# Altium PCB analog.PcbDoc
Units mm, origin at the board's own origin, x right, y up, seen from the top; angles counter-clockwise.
Board outline 152.4 x 101.6 mm, 2 copper layers (Top Layer, Bottom Layer); 110 components, 92 nets, 331 pads, 16 vias.
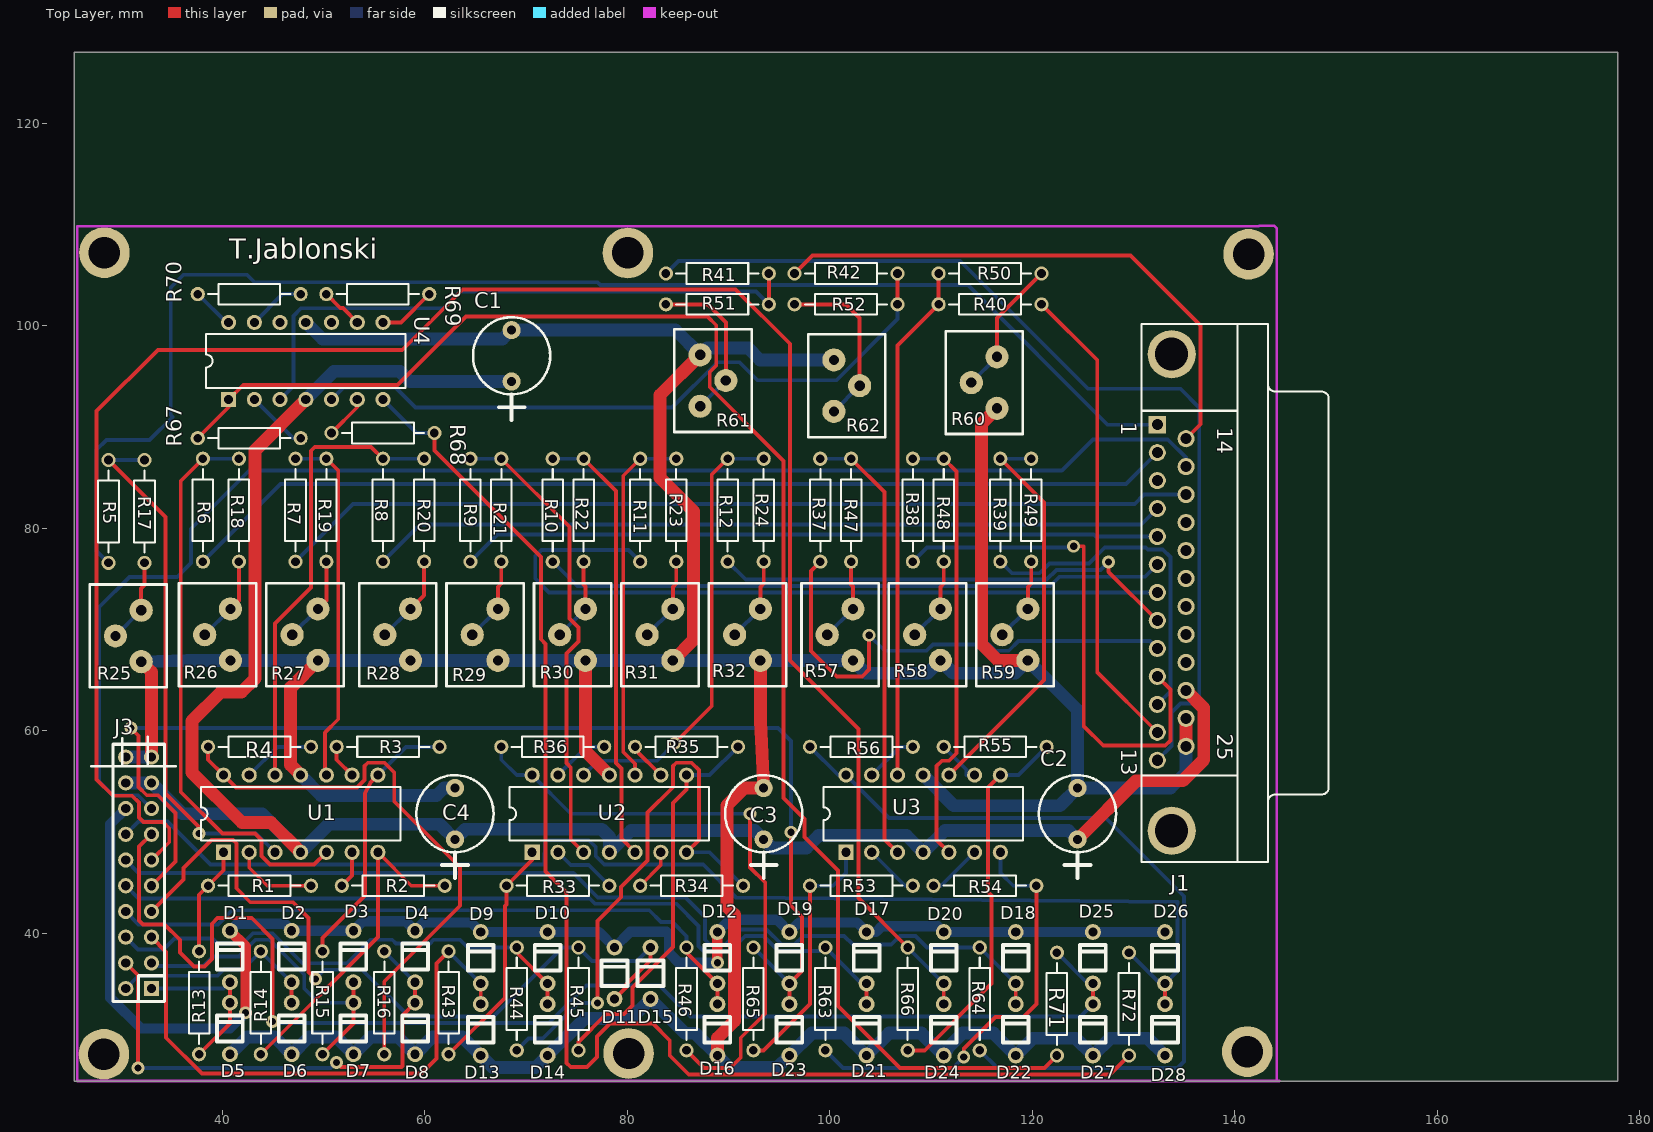
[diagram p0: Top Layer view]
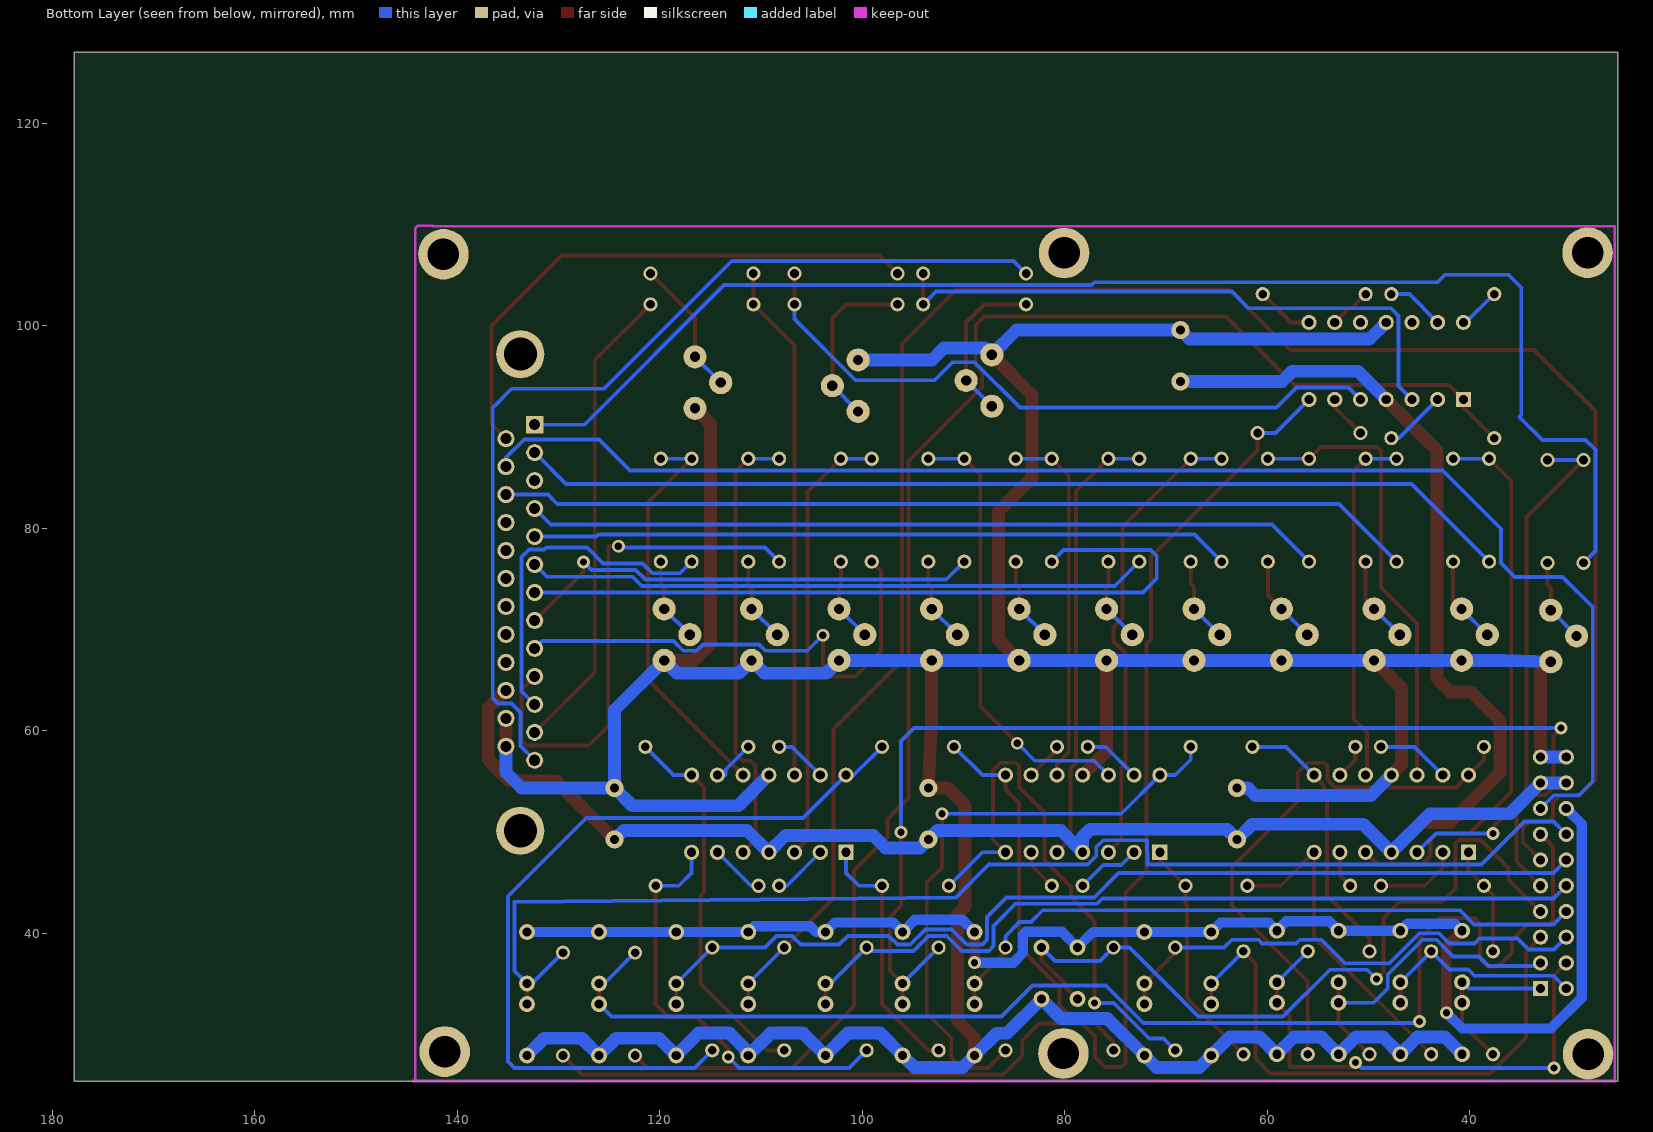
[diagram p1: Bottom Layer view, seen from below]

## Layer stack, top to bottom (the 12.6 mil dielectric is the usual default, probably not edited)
Top Layer: signal copper 0.0356
Dielectric: dielectric 0.32, FR-4, Dk 4.8
Bottom Layer: signal copper 0.0356

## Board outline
25.4,25.4 177.8,25.4 177.8,127 25.4,127

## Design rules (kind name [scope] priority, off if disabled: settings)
Clearance [All] p1: gap=0.254
PolygonConnect [All] p1: connectstyle=Relief reliefconductorwidth=0.254 reliefentries=4 polygonreliefangle="90 Angle"
RoutingVias [All] p1: holewidth=0.711 width=1.27 viastyle="Through Hole" minholewidth=0.711 minwidth=1.27 maxholewidth=0.711 maxwidth=1.27
SilkscreenOverComponentPads [All] p1: minsilkscreentomaskgap=0.254
SolderMaskExpansion [All] p1: expansion=0.102
Width +5V [InNet('+5V')] p1: maxlimit=1.27 minlimit=1.27 preferedwidth=1.27
Width GND [InNet('GND')] p2: maxlimit=1.27 minlimit=1.27 preferedwidth=1.27
Width +3,3V [InNet('+3,3V')] p3: maxlimit=1.016 minlimit=1.016 preferedwidth=1.016
Width all [All] p4: maxlimit=0.381 minlimit=0.381 preferedwidth=0.381
27 further rules are at their usual default settings.

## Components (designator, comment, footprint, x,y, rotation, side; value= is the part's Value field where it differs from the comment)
C1 "100u" RB.2/.3 68.58,94.488 r90 top
C2 "100u" RB.2/.3 124.46,49.276 r90 top
C3 "100u" RB.2/.3 93.472,49.276 r90 top
C4 "100u" RB.2/.3 62.992,49.276 r90 top
D1 "DIODE" DIODE0.2 40.767,35.179 r90 top
D2 "DIODE" DIODE0.2 46.863,35.179 r90 top
D3 "DIODE" DIODE0.2 52.959,35.179 r90 top
D4 "DIODE" DIODE0.2 59.055,35.179 r90 top
D5 "DIODE" DIODE0.2 40.767,28.067 r90 top
D6 "DIODE" DIODE0.2 46.863,28.067 r90 top
D7 "DIODE" DIODE0.2 52.959,28.067 r90 top
D8 "DIODE" DIODE0.2 59.055,28.067 r90 top
D9 "DIODE" DIODE0.2 65.532,35.052 r90 top
D10 "DIODE" DIODE0.2 72.136,35.052 r90 top
D11 "DIODE" DIODE0.2 78.74,33.528 r90 top
D12 "DIODE" DIODE0.2 88.9,35.052 r90 top
D13 "DIODE" DIODE0.2 65.532,27.94 r90 top
D14 "DIODE" DIODE0.2 72.136,27.94 r90 top
D15 "DIODE" DIODE0.2 82.296,33.528 r90 top
D16 "DIODE" DIODE0.2 88.9,27.94 r90 top
D17 "DIODE" DIODE0.2 103.632,35.052 r90 top
D18 "DIODE" DIODE0.2 118.364,35.052 r90 top
D19 "DIODE" DIODE0.2 96.012,35.052 r90 top
D20 "DIODE" DIODE0.2 111.252,35.052 r90 top
D21 "DIODE" DIODE0.2 103.632,27.94 r90 top
D22 "DIODE" DIODE0.2 118.364,27.94 r90 top
D23 "DIODE" DIODE0.2 96.012,27.94 r90 top
D24 "DIODE" DIODE0.2 111.252,27.94 r90 top
D25 "DIODE" DIODE0.2 125.984,35.052 r90 top
D26 "DIODE" DIODE0.2 133.096,35.052 r90 top
D27 "DIODE" DIODE0.2 125.984,27.94 r90 top
D28 "DIODE" DIODE0.2 133.096,27.94 r90 top
J1 "D Connector 25" DSUB1.385-2H25A 143.256,73.66 r270 top
J3 "analog" IDC20 33.02,34.544 r90 top
R1 "" AXIAL-0.4 43.688,44.704 r180 top
R2 "" AXIAL-0.4 56.896,44.704 r0 top
R3 "" AXIAL-0.4 56.388,58.42 r0 top
R4 "" AXIAL-0.4 43.688,58.42 r180 top
R5 "" AXIAL-0.4 28.778,81.661 r270 top
R6 "" AXIAL-0.4 38.1,81.788 r270 top
R7 "" AXIAL-0.4 47.244,81.788 r270 top
R8 "" AXIAL-0.4 55.88,81.788 r270 top
R9 "" AXIAL-0.4 64.516,81.788 r270 top
R10 "" AXIAL-0.4 72.644,81.788 r270 top
R11 "" AXIAL-0.4 81.28,81.788 r270 top
R12 "" AXIAL-0.4 89.916,81.788 r270 top
R13 "" AXIAL-0.4 37.719,33.147 r270 top
R14 "" AXIAL-0.4 43.815,33.147 r90 top
R15 "" AXIAL-0.4 49.911,33.147 r270 top
R16 "" AXIAL-0.4 56.007,33.147 r90 top
R17 "" AXIAL-0.4 32.334,81.661 r90 top
R18 "" AXIAL-0.4 41.656,81.788 r90 top
R19 "" AXIAL-0.4 50.292,81.788 r90 top
R20 "" AXIAL-0.4 59.944,81.788 r90 top
R21 "" AXIAL-0.4 67.564,81.788 r90 top
R22 "" AXIAL-0.4 75.692,81.788 r90 top
R23 "" AXIAL-0.4 84.836,81.788 r90 top
R24 "" AXIAL-0.4 93.472,81.788 r90 top
R25 "POT2" POT_HEL 31.318,69.469 r270 top
R26 "POT2" POT_HEL 40.132,69.596 r270 top
R27 "POT2" POT_HEL 48.768,69.596 r270 top
R28 "POT2" POT_HEL 57.912,69.596 r270 top
R29 "POT2" POT_HEL 66.548,69.596 r270 top
R30 "POT2" POT_HEL 75.184,69.596 r270 top
R31 "POT2" POT_HEL 83.82,69.596 r270 top
R32 "POT2" POT_HEL 92.456,69.596 r270 top
R33 "" AXIAL-0.4 73.152,44.704 r180 top
R34 "" AXIAL-0.4 86.36,44.704 r0 top
R35 "" AXIAL-0.4 85.852,58.42 r0 top
R36 "" AXIAL-0.4 72.644,58.42 r180 top
R37 "" AXIAL-0.4 99.06,81.788 r270 top
R38 "" AXIAL-0.4 108.204,81.788 r270 top
R39 "" AXIAL-0.4 116.84,81.788 r270 top
R40 "" AXIAL-0.4 115.824,102.108 r0 top
R41 "" AXIAL-0.4 88.9,105.156 r180 top
R42 "" AXIAL-0.4 101.6,105.156 r180 top
R43 "" AXIAL-0.4 62.357,33.147 r90 top
R44 "" AXIAL-0.4 69.088,33.528 r90 top
R45 "" AXIAL-0.4 75.184,33.528 r90 top
R46 "" AXIAL-0.4 85.852,33.528 r90 top
R47 "" AXIAL-0.4 102.108,81.788 r90 top
R48 "" AXIAL-0.4 111.252,81.788 r90 top
R49 "" AXIAL-0.4 119.888,81.788 r90 top
R50 "" AXIAL-0.4 115.824,105.156 r180 top
R51 "" AXIAL-0.4 88.9,102.108 r0 top
R52 "" AXIAL-0.4 101.6,102.108 r0 top
R53 "" AXIAL-0.4 103.124,44.704 r180 top
R54 "" AXIAL-0.4 115.316,44.704 r0 top
R55 "" AXIAL-0.4 116.332,58.42 r0 top
R56 "" AXIAL-0.4 103.124,58.42 r180 top
R57 "POT2" POT_HEL 101.6,69.596 r270 top
R58 "POT2" POT_HEL 110.236,69.596 r270 top
R59 "POT2" POT_HEL 118.872,69.596 r270 top
R60 "POT2" POT_HEL 115.824,94.488 r270 top
R61 "POT2" POT_HEL 87.884,94.488 r90 top
R62 "POT2" POT_HEL 101.092,93.98 r90 top
R63 "" AXIAL-0.4 99.568,33.528 r90 top
R64 "" AXIAL-0.4 114.808,33.528 r90 top
R65 "" AXIAL-0.4 92.456,33.528 r90 top
R66 "" AXIAL-0.4 107.696,33.528 r90 top
R67 "" AXIAL-0.4 42.672,88.9 r180 top
R68 "" AXIAL-0.4 55.88,89.408 r0 top
R69 "" AXIAL-0.4 55.372,103.124 r0 top
R70 "" AXIAL-0.4 42.672,103.124 r180 top
R71 "" AXIAL-0.4 122.428,33.02 r90 top
R72 "" AXIAL-0.4 129.54,33.02 r90 top
U1 "LM324AN" N014 47.752,51.816 r0 top
U2 "LM324AN" N014 78.232,51.816 r0 top
U3 "LM324AN" N014 109.22,51.816 r0 top
U4 "LM324AN" N014 48.26,96.52 r0 top

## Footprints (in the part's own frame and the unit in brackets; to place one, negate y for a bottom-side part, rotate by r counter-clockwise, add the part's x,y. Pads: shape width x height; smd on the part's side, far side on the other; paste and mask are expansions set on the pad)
AXIAL-0.4 [mm] "Axial Device, Thru-Hole; 2 Leads; 0.4 in Pin Spacing"
  round 1.4 hole 0.85: 1(-5.08,0) 2(5.08,0)
  silkscreen extent -4.06,-1.02 4.06,1.02
DIODE0.2 [mil]
  round 62 hole 35.43: A(0,0) K(200,0)
  silkscreen extent 50,-50 150,50
DSUB1.385-2H25A [mm] "Connector; D Subminiature; 25 Position; Right Angle; Pitch 1.385 mm"
  rect 1.69x1.69 hole 1.09: 1(-16.566,-10.92)
  round 1.69 hole 1.09: 2(-13.805,-10.92) 3(-11.044,-10.92) 4(-8.283,-10.92) 5(-5.522,-10.92) 6(-2.761,-10.92) 7(0,-10.92) 8(2.761,-10.92) 9(5.522,-10.92) 10(8.283,-10.92) 11(11.044,-10.92) 12(13.805,-10.92) 13(16.566,-10.92) 14(-15.185,-8.08) 15(-12.425,-8.08) 16(-9.663,-8.08) 17(-6.903,-8.08) 18(-4.142,-8.08) 19(-1.38,-8.08) 20(1.38,-8.08) 21(4.142,-8.08) 22(6.903,-8.08) 23(9.663,-8.08) 24(12.425,-8.08) 25(15.185,-8.08)
  round 4.76 hole 3.26: 26(-23.526,-9.5) 27(23.526,-9.5)
  silkscreen extent -26.5,-12.5 26.6,6
IDC20 [mm]
  rect 1.5x1.5 hole 0.9: 1(0,0)
  round 1.5 hole 0.9: 2(0,2.54) 3(2.54,0) 4(2.54,2.54) 5(5.08,0) 6(5.08,2.54) 7(7.62,0) 8(7.62,2.54) 9(10.16,0) 10(10.16,2.54) 11(12.7,0) 12(12.7,2.54) 13(15.24,0) 14(15.24,2.54) 15(17.78,0) 16(17.78,2.54) 17(20.32,0) 18(20.32,2.54) 19(22.86,0) 20(22.86,2.54)
  silkscreen extent -1.27,-1.27 24.13,3.81
N014 [mm] "DIP; 14 Leads; Row Spacing 7.62 mm; Pitch 2.54 mm"
  rect 1.5x1.5 hole 0.9: 1(-7.62,-3.81)
  round 1.5 hole 0.9: 2(-5.08,-3.81) 3(-2.54,-3.81) 4(0,-3.81) 5(2.54,-3.81) 6(5.08,-3.81) 7(7.62,-3.81) 8(7.62,3.81) 9(5.08,3.81) 10(2.54,3.81) 11(0,3.81) 12(-2.54,3.81) 13(-5.08,3.81) 14(-7.62,3.81)
  silkscreen extent -9.85,-2.65 9.85,2.65
POT_HEL [mil]
  round 90 hole 40: 1(104,27) 2(-96,27) 3(4,-73)
  silkscreen extent -196,-173 204,127
RB.2/.3 [mm]
  round 1.8 hole 0.9: 1(0,0) 2(5.08,0)
  silkscreen extent -3.81,-3.81 6.35,3.81

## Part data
C1 C2 C3 C4: library part ELECTRO2, "Electrolytic Capacitor"
D1 D2 D3 D4 D5 D6 D7 D8 D9 D10 D11 D12 D13 D14 D15 D16 D17 D18 D19 D20 D21 D22 D23 D24 D25 D26 D27 D28: "Diode"
J1: "Receptacle Assembly, 25 Position, Right Angle"
J3: library part 20PIN
R1 R2 R3 R4 R5 R6 R7 R8 R9 R10 R11 R12 R13 R14 R15 R16 R17 R18 R19 R20 R21 R22 R23 R24 R33 R34 R35 R36 R37 R38 R39 R40 R41 R42 R43 R44 R45 R46 R47 R48 R49 R50 R51 R52 R53 R54 R55 R56 R63 R64 R65 R66 R67 R68 R69 R70 R71 R72: library part res2, "Resistor"
R25 R26 R27 R28 R29 R30 R31 R32 R57 R58 R59 R60 R61 R62: "Potentiometer"
U1 U2 U3 U4: "Quadruple Operational Amplifier"

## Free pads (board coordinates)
  round 5 hole 3.1: 0(80.137,28.143) 0(141.224,28.321) 1(28.321,28.067) 1(141.351,107.061) 2(80.061,107.188) 3(28.372,107.213)

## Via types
v1: diameter 1.27, hole 0.711, Top Layer to Bottom Layer, 16 vias

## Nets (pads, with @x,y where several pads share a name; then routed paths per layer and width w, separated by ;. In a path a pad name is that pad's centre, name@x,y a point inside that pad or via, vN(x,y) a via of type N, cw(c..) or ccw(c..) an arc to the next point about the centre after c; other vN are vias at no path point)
+3,3V: D1.K D2.K D3.K D4.K D9.K D10.K D11.K D12.K D17.K D18.K D19.K D20.K D25.K D26.K J3.16 | length 146.6
  Top Layer w1.016: D1.K 42.316,38.71 v1(42.316,32.156) ; v1(88.9,37.109) D12.K
  Bottom Layer w1.016: J3.16 28.956,50.8 28.956,33.655 32.004,30.607 40.767,30.607 v1(42.316,32.156) ; D1.K 41.467,40.959 46.163,40.959 D2.K D3.K 53.899,41.199 58.115,41.199 D4.K 59.868,41.072 64.592,41.072 D9.K D10.K 77.216,40.132 D11.K 80.289,40.157 83.845,40.157 84.125,39.878 84.125,38.075 85.09,37.109 v1(88.9,37.109) ; D12.K 90.108,41.34 94.804,41.34 D19.K 96.952,41.072 102.692,41.072 D17.K 104.572,40.132 105.145,40.705 110.679,40.705 D20.K D18.K D25.K D26.K
+5V: C1.1 C2.1 C3.1 C4.1 J1.23 J3.17 J3.18 U1.4 U2.4 U3.4 U4.4 | length 206.8
  Top Layer w1.27: U1.4 44.818,50.94 41.948,50.94 37.008,55.88 37.008,60.96 39.878,63.83 41.91,63.83 43.256,65.176 43.256,87.706 U4.4 ; C2.1 130.251,55.067 134.849,55.067 136.931,57.15 136.931,62.241 J1.23
  Bottom Layer w1.27: J3.18 J3.17 36.068,51.816 43.942,51.816 U1.4 50.521,50.775 61.493,50.775 C4.1 63.996,50.28 77.482,50.28 78.232,49.53 U2.4 80.381,50.155 92.593,50.155 C3.1 94.3,48.448 97.689,48.448 98.898,49.657 107.569,49.657 U3.4 111.379,50.165 123.571,50.165 C2.1 ; U4.4 51.054,95.504 57.544,95.504 58.56,94.488 C1.1
A1: J1.1 R5.2 | length 137.4
  Bottom Layer w0.381: R5.2 27.61,77.749 27.61,87.757 28.575,88.722 32.842,88.722 35.115,90.995 34.925,91.186 34.925,103.759 36.195,105.029 42.443,105.029 43.18,104.292 77.064,104.292 77.345,104.011 113.641,104.011 127.427,90.226 J1.1
A2: J1.2 R6.2 | length 98.7
  Bottom Layer w0.381: R6.2 45.771,84.379 129.25,84.379 J1.2
A3: J1.16 R7.2 | length 90.7
  Bottom Layer w0.381: R7.2 52.934,82.398 130.113,82.398 131.039,83.323 J1.16
A4: J1.4 R8.2 | length 78.6
  Bottom Layer w0.381: R8.2 59.538,80.366 130.759,80.366 J1.4
A5: J1.5 R9.2 | length 69
  Bottom Layer w0.381: R9.2 67.183,79.375 126.07,79.375 126.263,79.182 J1.5
A6: J1.6 R10.2 | length 61.6
  Bottom Layer w0.381: R10.2 75.059,74.293 121.77,74.293 122.686,75.209 131.124,75.209 J1.6
A7: J1.7 R11.2 | length 75.3
  Bottom Layer w0.381: R11.2 80.135,77.853 71.515,77.853 70.917,77.254 70.917,75.032 72.29,73.658 122.934,73.658 122.936,73.66 J1.7
A8: J1.8 R12.2 | length 46.9
  Top Layer w0.381: v1(127.533,76.683) 127.533,75.702 J1.8
  Bottom Layer w0.381: R12.2 91.696,74.928 121.41,74.928 122.377,75.895 126.746,75.895 v1(127.533,76.683)
A9: J1.9 R37.2 | length 50
  Top Layer w0.381: R37.2 98.146,75.794 98.146,67.894 100.686,65.354 103.2,65.354 103.886,66.04 v1(103.886,69.444)
  Bottom Layer w0.381: v1(103.886,69.444) 105.423,67.907 109.537,67.907 110.172,68.542 115.725,68.542 116.36,67.907 117.675,67.907 118.628,68.859 131.615,68.859 J1.9
A10: J1.10 R38.2 | length 51.7
  Top Layer w0.381: v1(124.079,78.232) 125.07,78.232 125.07,60.477 127,58.547 133.121,58.547 133.629,59.055 133.629,64.084 J1.10
  Bottom Layer w0.381: R38.2 109.601,78.105 123.952,78.105 v1(124.079,78.232)
A11: J1.11 R39.2 | length 33.8
  Bottom Layer w0.381: R39.2 117.985,75.563 120.714,75.563 121.69,76.539 125.583,76.539 127.149,78.105 131.191,78.105 131.403,77.893 132.87,77.893 132.88,77.902 133.629,77.153 133.629,63.909 J1.11
A12: J1.12 R40.2 | length 47
  Top Layer w0.381: R40.2 126.416,96.596 126.416,65.775 J1.12
A13: J1.13 R41.2 | length 96.5
  Bottom Layer w0.381: R41.2 85.065,106.401 112.878,106.401 125.501,93.777 134.62,93.777 136.474,91.923 136.474,63.182 135.979,62.687 134.62,62.687 133.756,61.824 133.756,58.514 J1.13
A14: J1.14 R42.2 | length 55.4
  Top Layer w0.381: R42.2 98.298,106.934 129.692,106.934 136.601,100.025 136.601,90.271 J1.14
AIIN1: D1.A D5.K J3.1 R13.2 | length 16.4
  Top Layer w0.381: R13.2 40.767,31.115 D5.K D1.A
  Bottom Layer w0.381: J3.1 40.132,34.544 D1.A
AIIN2: D2.A D6.K J3.2 R14.2 | length 21.2
  Top Layer w0.381: D6.K D2.A
  Bottom Layer w0.381: J3.2 31.75,35.814 39.548,35.814 40.157,36.424 42.012,36.424 R14.2 D2.A
AIIN3: D3.A D7.K J3.3 R15.2 | length 32.9
  Top Layer w0.381: R15.2 52.959,31.115 D7.K D3.A
  Bottom Layer w0.381: J3.3 33.325,36.779 38.151,36.779 39.091,37.719 41.654,37.719 43.307,39.372 44.664,39.372 48.108,35.928 48.108,34.569 49.53,33.147 D7.K
AIIN4: D4.A D8.K J3.4 R16.2 | length 50.6
  Top Layer w0.381: J3.4 31.699,35.865 v1(31.699,26.695) ; v1(51.283,27.254) 51.714,26.822 57.734,26.822 57.81,26.899 57.81,31.902 D8.K D4.A
  Bottom Layer w0.381: v1(31.699,26.695) 50.724,26.695 v1(51.283,27.254) ; R16.2 D4.A
AIIN5: D9.A D13.K J3.5 R43.2 | length 56.9
  Top Layer w0.381: J3.5 34.468,38.176 34.468,29.693 37.998,26.162 59.69,26.162 61.163,27.635 61.163,37.033 R43.2 ; D13.K D9.A
  Bottom Layer w0.381: R43.2 D9.A
AIIN6: D10.A D14.K J3.6 R44.2 | length 49.8
  Top Layer w0.381: R44.2 69.088,38.1 D10.A D14.K
  Bottom Layer w0.381: J3.6 31.699,38.405 34.214,38.405 35.306,39.497 39.065,39.497 39.548,39.014 42.035,39.014 43.028,40.007 44.958,40.007 47.919,37.046 52.31,37.046 54.635,39.372 56.793,39.372 57.15,39.014 60.527,39.014 60.884,39.372 63.5,39.372 64.264,38.608 R44.2
AIIN7: D11.A D15.K J3.7 R45.2 | length 77.1
  Top Layer w0.381: J3.7 36.179,45.323 36.179,46.466 38.938,49.225 41.072,49.225 41.402,48.895 41.402,44.45 42.774,43.078 46.99,43.078 48.539,41.529 48.539,36.195 v1(49.225,35.509) ; D11.A 79.883,34.671 79.883,34.934 82.296,37.347 D15.K
  Bottom Layer w0.381: v1(49.225,35.509) 50.127,36.411 53.81,36.411 58.433,31.788 66.777,31.788 73.596,38.608 R45.2 76.53,37.262 80.95,37.262 D15.K
AIIN8: D12.A D16.K J3.8 R46.2 | length 65.5
  Top Layer w0.381: R46.2 85.852,38.1 D12.A D16.K
  Bottom Layer w0.381: J3.8 31.75,40.894 39.575,40.894 40.97,42.289 82.171,42.289 83.35,41.11 84.455,41.11 85.852,39.713 R46.2
AIIN9: D19.A D23.K J3.9 R65.2 | length 116.7
  Top Layer w0.381: v1(30.988,60.274) 31.75,59.512 31.75,54.445 32.55,53.645 33.655,53.645 35.408,51.892 35.408,47.092 J3.9 ; D23.K D19.A 97.257,36.297 97.257,41.631 96.164,42.723 v1(96.164,49.987)
  Bottom Layer w0.381: v1(30.988,60.274) 94.869,60.274 96.164,58.979 v1(96.164,49.987) ; R65.2 D19.A
AIIN10: D17.A D21.K J3.10 R63.2 | length 82.1
  Top Layer w0.381: D21.K D17.A
  Bottom Layer w0.381: J3.10 31.75,43.434 76.3,43.434 76.81,42.924 84.848,42.924 87.033,40.739 87.033,38.735 87.503,38.265 90.17,38.265 91.657,39.753 93.453,39.753 94.94,38.265 99.444,38.265 99.444,38.608 R63.2 103.124,35.052 D17.A
AIIN11: D20.A D24.K J3.11 R66.2 | length 197.4
  Top Layer w0.381: J3.11 34.773,48.997 34.773,50.385 34.154,51.003 32.233,51.003 31.801,51.435 31.801,52.908 31.115,53.594 29.21,53.594 27.61,55.194 27.61,91.567 33.655,97.612 57.785,97.612 63.754,103.581 90.703,103.581 96.063,98.222 96.063,66.929 102.819,60.173 102.819,43.485 R66.2 ; D24.K D20.A
  Bottom Layer w0.381: R66.2 D20.A
AIIN12: D18.A D22.K J3.12 R64.2 | length 98.9
  Top Layer w0.381: D22.K D18.A
  Bottom Layer w0.381: J3.12 31.75,45.974 74.674,45.974 77.089,43.559 85.739,43.559 87.668,41.631 87.668,39.37 88.138,38.9 89.675,38.9 91.162,40.388 93.763,40.388 95.25,38.9 96.533,38.9 97.385,39.753 101.421,39.753 102.286,38.887 106.07,38.887 106.936,39.753 108.456,39.753 109.601,38.608 R64.2 D18.A
AIIN13: D25.A D27.K J3.13 R71.2 | length 129.1
  Top Layer w0.381: J3.13 31.801,48.565 31.801,41.275 32.182,40.894 34.315,40.894 35.839,39.37 35.839,38.1 37.211,36.728 38.252,36.728 38.989,37.465 38.989,40.945 39.548,41.504 42.926,41.504 44.983,39.446 v1(44.983,31.293) ; D27.K D25.A
  Bottom Layer w0.381: v1(44.983,31.293) 45.123,31.153 72.25,31.153 75.946,34.849 83.185,34.849 86.258,31.775 124.739,31.775 D27.K ; R71.2 125.476,35.052 D25.A
AIIN14: D26.A D28.K J3.14 R72.2 | length 126.8
  Top Layer w0.381: D28.K D26.A
  Bottom Layer w0.381: J3.14 31.75,51.054 34.595,51.054 38.862,46.787 71.831,46.787 71.882,49.201 76.2,49.201 76.887,48.514 76.887,47.625 77.725,46.787 87.503,46.787 90.754,43.536 134.341,43.104 134.341,36.297 D26.A 132.588,35.052 R72.2
B1: R5.1 R17.2 U1.3 | length 52.4
  Top Layer w0.381: R5.1 34.417,81.102 34.417,53.795 37.719,50.493 v1(37.719,49.86)
  Bottom Layer w0.381: R5.1 R17.2 ; v1(37.719,49.86) 43.358,49.86 U1.3
B2: R6.1 R18.2 U1.5 | length 56.1
  Top Layer w0.381: R6.1 35.916,84.684 35.916,53.976 40.031,49.86 43.256,49.86 43.891,49.225 43.891,47.625 44.729,46.787 49.073,46.787 U1.5
  Bottom Layer w0.381: R6.1 R18.2
B3: R7.1 R19.2 U1.10 | length 35.5
  Top Layer w0.381: U1.10 50.14,55.626 50.14,59.817 51.46,61.138 51.46,85.7 R19.2
  Bottom Layer w0.381: R7.1 R19.2
B4: R8.1 R20.2 U1.12 | length 45.3
  Top Layer w0.381: U1.12 45.212,70.612 48.768,74.168 48.768,87.655 49.149,88.036 54.712,88.036 R8.1
  Bottom Layer w0.381: R8.1 R20.2
B5: R9.1 R21.2 U2.3 | length 46.3
  Top Layer w0.381: R21.2 74.282,80.15 74.282,71.095 75.184,70.193 75.184,68.834 73.99,67.64 73.99,56.82 74.422,56.388 74.422,49.276 U2.3
  Bottom Layer w0.381: R9.1 R21.2
B6: R10.1 R22.2 U2.5 | length 44
  Top Layer w0.381: R22.2 78.892,83.668 78.892,56.82 79.427,56.286 79.427,49.351 U2.5
  Bottom Layer w0.381: R10.1 R22.2
B7: R11.1 R23.2 U2.10 | length 36
  Top Layer w0.381: U2.10 80.772,56.745 79.604,57.913 79.604,85.192 R11.1
  Bottom Layer w0.381: R11.1 R23.2
B8: R12.1 R24.2 U2.12 | length 44.1
  Top Layer w0.381: v1(84.684,58.776) 88.341,62.433 88.341,85.293 R12.1
  Bottom Layer w0.381: U2.12 77.114,57.048 82.956,57.048 v1(84.684,58.776) ; R12.1 R24.2
B9: R37.1 R47.2 U3.3 | length 43.8
  Top Layer w0.381: R47.2 105.41,83.566 105.41,49.276 U3.3
  Bottom Layer w0.381: R37.1 R47.2
B10: R38.1 R48.2 U3.5 | length 44.2
  Top Layer w0.381: R48.2 112.522,85.598 112.522,57.785 111.785,57.048 111.074,57.048 110.541,56.515 110.541,49.225 U3.5
  Bottom Layer w0.381: R38.1 R48.2
B11: R39.1 R49.2 U3.10 | length 40
  Top Layer w0.381: U3.10 121.158,65.024 121.158,82.55 R39.1
  Bottom Layer w0.381: R39.1 R49.2
B12: R40.1 R50.2 U3.12 | length 51.2
  Top Layer w0.381: U3.12 106.68,98.044 R40.1 R50.2
B13: R41.1 R51.2 U4.3 | length 60.3
  Top Layer w0.381: R51.2 R41.1
  Bottom Layer w0.381: U4.3 47.041,94.031 47.041,100.965 47.803,101.727 61.849,101.727 63.498,103.376 92.712,103.376 R51.2
B14: R42.1 R52.2 U4.5 | length 66.8
  Top Layer w0.381: R52.2 R42.1
  Bottom Layer w0.381: U4.5 51.995,93.905 57.099,93.905 59.081,91.923 84.43,91.923 88.9,96.393 91.084,96.393 92.862,94.615 100.645,94.615 106.68,100.65 R52.2
C1: R1.2 R13.1 U1.1 | length 10.8
  Top Layer w0.381: R13.1 37.719,43.815 R1.2 40.132,46.228 U1.1
C2: R2.2 R14.1 U1.7 | length 32.7
  Top Layer w0.381: R14.1 55.372,39.624 U1.7 58.674,44.704 R2.2
C3: R3.2 R15.1 U1.8 | length 26.8
  Top Layer w0.381: R15.1 49.911,39.548 54.102,43.739 54.102,53.796 54.662,54.916 U1.8
  Bottom Layer w0.381: U1.8 58.166,58.42 R3.2
C4: R4.2 R16.1 U1.14 | length 56.6
  Top Layer w0.381: R4.2 38.608,57.15 U1.14 41.351,54.407 53.315,54.407 54.051,55.143 54.051,56.515 54.381,56.845 56.032,56.845 56.998,55.88 56.998,53.035 63.5,46.533 63.5,42.723 56.007,35.23 R16.1
C5: R33.2 R43.1 U2.1 | length 23.4
  Top Layer w0.381: R43.1 67.92,33.63 67.92,42.697 68.072,42.85 R33.2 70.612,47.244 U2.1
C6: R34.2 R44.1 U2.7 | length 55
  Top Layer w0.381: v1(77.064,33.122) 77.064,41.224 79.4,43.561 79.4,44.577 82.017,47.193 82.017,51.942 84.507,54.432 84.507,56.515 84.837,56.845 86.36,56.845 87.071,56.134 87.071,49.225 U2.7
  Bottom Layer w0.381: R44.1 70.256,29.616 71.653,29.616 75.159,33.122 v1(77.064,33.122) ; U2.7 88.138,48.006 R34.2
C7: R35.2 R45.1 U2.8 | length 38.9
  Top Layer w0.381: R45.1 75.184,29.287 77.922,32.024 79.675,32.024 80.518,32.868 80.518,34.671 84.506,38.659 84.506,52.878 85.852,54.224 U2.8
  Bottom Layer w0.381: U2.8 88.138,55.626 R35.2
C8: R36.2 R46.1 U2.14 | length 60.2
  Top Layer w0.381: R46.1 87.592,26.708 90.17,26.708 91.211,27.749 91.211,29.693 93.624,32.106 93.624,45.009 92.126,46.507 v1(92.126,51.816)
  Bottom Layer w0.381: R36.2 67.564,57.15 69.088,55.626 U2.14 74.422,51.816 v1(92.126,51.816)
C9: R53.2 R65.1 U3.1 | length 25.3
  Top Layer w0.381: R65.1 93.472,28.448 98.044,33.02 R53.2
  Bottom Layer w0.381: R53.2 100.33,44.704 101.6,45.974 U3.1
C10: R54.2 R63.1 U3.7 | length 42.5
  Top Layer w0.381: v1(113.233,27.788) 113.233,28.626 116.357,31.75 119.126,31.75 120.396,33.02 R54.2
  Bottom Layer w0.381: R63.1 101.321,26.695 112.141,26.695 v1(113.233,27.788) ; U3.7 116.84,45.974 118.11,44.704 R54.2
C11: R55.2 R66.1 U3.8 | length 38
  Top Layer w0.381: R66.1 109.372,28.448 115.976,35.052 115.976,43.739 115.621,44.094 115.621,54.407 U3.8
  Bottom Layer w0.381: U3.8 118.618,55.626 R55.2
C12: R56.2 R64.1 U3.14 | length 80.5
  Bottom Layer w0.381: R56.2 100.838,55.626 U3.14 105.842,51.384 127.254,51.384 134.976,43.663 134.976,27.33 134.341,26.695 116.561,26.695 R64.1
C13: R67.2 R71.1 U4.1 | length 154.4
  Top Layer w0.381: R67.2 40.64,91.948 U4.1 42.088,94.158 57.328,94.158 64.084,100.914 87.922,100.914 88.786,100.051 88.786,96.063 88.151,95.428 88.151,93.932 95.428,86.655 95.428,53.353 97.487,51.294 97.487,49.529 100.813,46.203 100.813,32.842 106.947,26.708 121.196,26.708 R71.1
C14: R68.2 R72.1 U4.7 | length 136.5
  Top Layer w0.381: R68.2 60.96,87.681 71.476,77.165 71.476,69.037 71.933,68.58 71.933,46.101 74.016,44.018 74.016,27.203 74.422,26.797 76.022,26.797 77.012,27.787 77.012,29.82 78.282,31.09 82.55,31.09 84.201,29.439 84.201,27.94 86.068,26.073 127.673,26.073 R72.1
  Bottom Layer w0.381: U4.7 59.182,89.408 R68.2
C15: R69.2 U4.8 | length 5.7
  Top Layer w0.381: U4.8 57.658,100.33 R69.2
C16: R70.2 U4.14 | length 4.1
  Bottom Layer w0.381: R70.2 U4.14@40.513,100.203
DS1820: J1.15 J3.15 | length 141.3
  Bottom Layer w0.381: J3.15 31.699,53.645 29.21,53.645 27.864,54.991 27.864,72.212 30.836,75.184 35.56,75.184 36.932,76.556 36.932,79.959 42.672,85.7 122.911,85.7 125.984,88.773 133.375,88.773 135.176,86.972 J1.15
GND: C1.2 C2.2 C3.2 C4.2 D5.A D6.A D7.A D8.A D13.A D14.A D15.A D16.A D21.A D22.A D23.A D24.A D27.A D28.A J1.24 J1.25 J3.19 J3.20 R25.1 R26.1 R27.1 R28.1 R29.1 R30.1 R31.1 R32.1 R57.1 R58.1 R59.1 R60.1 R61.1 R62.1 U1.11 U2.11 U3.11 U4.11 | length 466
  Top Layer w1.27: R25.1 33.02,65.811 J3.19 ; U1.11 46.761,56.617 46.761,64.262 R27.1 ; R30.1 75.87,57.988 U2.11 ; R31.1 86.538,68.986 86.538,81.686 83.236,84.988 83.236,93.167 R61.1 ; D16.A 88.9,29.667 90.576,31.344 90.576,41.859 89.84,42.596 89.84,52.643 91.553,54.356 C3.2 93.142,60.985 R32.1 ; R60.1 114.986,90.322 114.986,68.58 116.611,66.954 R59.1 ; J1.25 J1.24
  Bottom Layer w1.27: J3.20 J3.19 ; R25.1 36.551,66.954 R26.1 R27.1 R28.1 R29.1 R30.1 R31.1 R32.1 R57.1 103.556,65.684 109.652,65.684 R58.1 112.192,65.684 118.288,65.684 R59.1 124.46,62.052 C2.2 ; D5.A 42.469,29.769 45.161,29.769 D6.A 48.565,29.769 51.257,29.769 D7.A 54.661,29.769 57.353,29.769 D8.A 60.757,29.769 63.703,29.769 D13.A 66.726,26.746 70.942,26.746 D14.A 75.776,31.58 80.348,31.58 D15.A 85.69,30.134 86.706,30.134 D16.A 90.094,26.746 94.818,26.746 D23.A 98.222,30.15 101.422,30.15 D21.A 105.842,30.15 109.042,30.15 D24.A 111.695,28.73 113.115,30.15 116.154,30.15 D22.A 120.066,29.642 124.282,29.642 D27.A 127.686,29.642 131.394,29.642 D28.A ; U1.11 49.759,53.619 61.163,53.619 61.9,54.356 C4.2 ; U4.11 49.911,98.679 67.691,98.679 C1.2 84.76,99.568 R61.1 87.859,97.79 91.948,97.79 93.116,96.622 R62.1 ; U3.11 112.243,52.603 122.707,52.603 C2.2 ; J1.25 135.176,55.88 133.652,54.356 C2.2
NetR1_1: R1.1 U1.2 | length 8.4
  Top Layer w0.381: U1.2 42.672,46.482 44.45,44.704 R1.1
NetR2_1: R2.1 U1.6 | length 3.7
  Top Layer w0.381: R2.1 52.832,45.72 U1.6
NetR3_1: R3.1 U1.9 | length 3.4
  Top Layer w0.381: R3.1 51.308,57.15 U1.9
NetR4_1: R4.1 U1.13 | length 7.3
  Bottom Layer w0.381: U1.13 45.466,58.42 R4.1
NetR17_1: R17.1 R25.2 R25.3 | length 8.4
  Top Layer w0.381: R25.2 32.004,74.066 32.334,74.397 R17.1
  Bottom Layer w0.381: R25.3 R25.2
NetR18_1: R18.1 R26.2 R26.3 | length 8.6
  Top Layer w0.381: R26.2 41.656,72.873 R18.1
  Bottom Layer w0.381: R26.3 R26.2
NetR19_1: R19.1 R27.2 R27.3 | length 8.6
  Top Layer w0.381: R27.2 50.292,72.873 R19.1
  Bottom Layer w0.381: R27.3 R27.2
NetR20_1: R20.1 R28.2 R28.3 | length 8.8
  Top Layer w0.381: R28.2 59.944,73.381 R20.1
  Bottom Layer w0.381: R28.3 R28.2
NetR21_1: R21.1 R29.2 R29.3 | length 8.4
  Top Layer w0.381: R29.2 67.234,74.193 67.564,74.524 R21.1
  Bottom Layer w0.381: R29.3 R29.2
NetR22_1: R22.1 R30.2 R30.3 | length 8.3
  Top Layer w0.381: R22.1 75.692,74.447 75.87,74.27 R30.2
  Bottom Layer w0.381: R30.3 R30.2
NetR23_1: R23.1 R31.2 R31.3 | length 8.4
  Top Layer w0.381: R31.2 84.506,74.193 84.836,74.524 R23.1
  Bottom Layer w0.381: R31.3 R31.2
NetR24_1: R24.1 R32.2 R32.3 | length 8.4
  Top Layer w0.381: R32.2 93.142,74.193 93.472,74.524 R24.1
  Bottom Layer w0.381: R32.3 R32.2
NetR33_1: R33.1 U2.2 | length 6.4
  Bottom Layer w0.381: U2.2 74.422,46.736 76.2,46.736 R33.1
NetR34_1: R34.1 U2.6 | length 4.1
  Top Layer w0.381: R34.1 83.312,46.736 U2.6
NetR35_1: R35.1 U2.9 | length 3.8
  Top Layer w0.381: R35.1 80.772,58.166 U2.9
NetR36_1: R36.1 U2.13 | length 5.7
  Bottom Layer w0.381: U2.13 75.946,58.42 R36.1
NetR47_1: R47.1 R57.2 R57.3 | length 8.3
  Top Layer w0.381: R47.1 102.108,74.447 102.286,74.27 R57.2
  Bottom Layer w0.381: R57.3 R57.2
NetR48_1: R48.1 R58.2 R58.3 | length 8.4
  Top Layer w0.381: R58.2 110.922,74.193 111.252,74.524 R48.1
  Bottom Layer w0.381: R58.3 R58.2
NetR49_1: R49.1 R59.2 R59.3 | length 8.4
  Top Layer w0.381: R59.2 119.558,74.193 119.888,74.524 R49.1
  Bottom Layer w0.381: R59.3 R59.2
NetR50_1: R50.1 R60.2 R60.3 | length 13.6
  Top Layer w0.381: R60.2 116.51,100.762 R50.1
  Bottom Layer w0.381: R60.3 R60.2
NetR51_1: R51.1 R61.2 R61.3 | length 16
  Top Layer w0.381: R51.1 87.96,102.108 89.738,100.33 R61.3
  Bottom Layer w0.381: R61.2 R61.3
NetR52_1: R52.1 R62.2 R62.3 | length 17.3
  Top Layer w0.381: R52.1 101.6,102.108 102.946,100.762 R62.3
  Bottom Layer w0.381: R62.2 R62.3
NetR53_1: R53.1 U3.2 | length 5.4
  Bottom Layer w0.381: U3.2 107.442,44.704 R53.1
NetR54_1: R54.1 U3.6 | length 5.4
  Bottom Layer w0.381: R54.1 110.998,44.704 U3.6
NetR55_1: R55.1 U3.9 | length 4.5
  Bottom Layer w0.381: R55.1 113.513,56.159 113.513,55.626 U3.9
NetR56_1: R56.1 U3.13 | length 5.2
  Bottom Layer w0.381: U3.13 106.934,58.42 R56.1
NetR67_1: R67.1 U4.2 | length 6.2
  Bottom Layer w0.381: U4.2 46.99,88.9 R67.1
NetR68_1: R68.1 U4.6 | length 4.4
  Top Layer w0.381: R68.1 53.34,91.948 U4.6
NetR69_1: R69.1 U4.9 | length 4.2
  Top Layer w0.381: R69.1 51.664,101.752 51.918,101.752 U4.9
NetR70_1: R70.1 U4.13 | length 5.7
  Bottom Layer w0.381: U4.13 45.974,103.124 R70.1
pads on no net: J1.3 J1.17 J1.18 J1.19 J1.20 J1.21 J1.22 J1.26 J1.27 U4.10 U4.12

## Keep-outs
Keep-Out Layer:
  lines w0.254: 25.679,25.425 144.399,25.425 ; 25.679,25.578 25.679,109.83 142.367,109.83 ; 142.392,109.855 143.891,109.855 144.145,109.601 144.145,25.425

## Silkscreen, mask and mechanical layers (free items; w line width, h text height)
Top Overlay:
  lines w0.254: 27.076,56.49 30.124,56.49 ; 30.124,59.284 30.124,56.49 ; 32.664,56.49 32.664,59.411 ; 35.433,56.515 35.408,56.49 30.124,56.49
  text "T.Jablonski" at 40.691,106.629 h2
